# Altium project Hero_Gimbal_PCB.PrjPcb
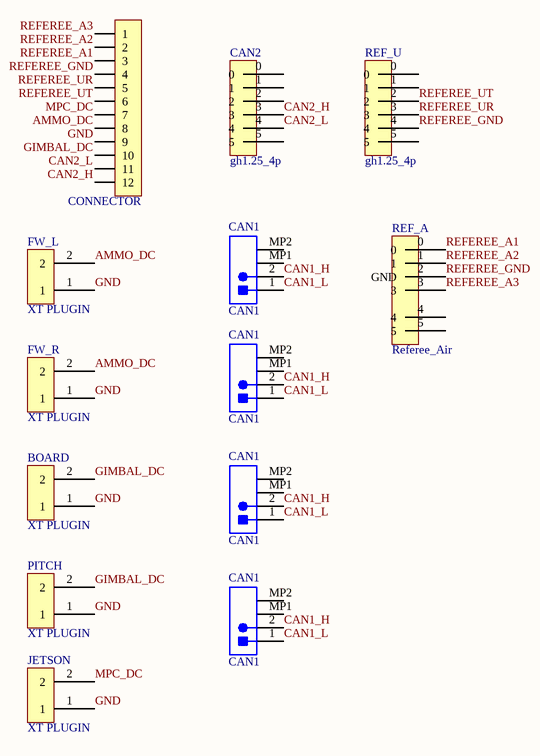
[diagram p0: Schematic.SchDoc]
1 sheet, 13 parts. Net scope: global (net labels, ports and power ports of the same name join across sheets).
Board file: hero gimbal pcb.PcbDoc

## Sheet Schematic.SchDoc
size A4

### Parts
(Parts that share a designator on the sheet are numbered #1, #2 ... from top to bottom, then left to right.)
BOARD  XT PLUGIN  [XT30-M]
CAN1#1  CAN1  [JST-BM02B-GHS-TBT_V]
CAN1#2  CAN1  [JST-BM02B-GHS-TBT_V]
CAN1#3  CAN1  [JST-BM02B-GHS-TBT_V]
CAN1#4  CAN1  [JST-BM02B-GHS-TBT_V]
CAN2  gh1.25_4p  [GH1.25-LS-4P]
CONNECTOR  HDR-1X12  [KF2EDGK5.08-LI-12P]  (value not drawn)
FW_L  XT PLUGIN  [XT30-M]
FW_R  XT PLUGIN  [XT30-M]
JETSON  XT PLUGIN  [XT30-M]
PITCH  XT PLUGIN  [XT30-M]
REF_A  Referee_Air  [M8 Connector]
REF_U  gh1.25_4p  [GH1.25-LS-4P]

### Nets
AMMO_DC: CONNECTOR.8 FW_L.2 FW_R.2
CAN1_H: CAN1#1.2 CAN1#2.2 CAN1#3.2 CAN1#4.2
CAN1_L: CAN1#1.1 CAN1#2.1 CAN1#3.1 CAN1#4.1
CAN2_H: CAN2.3 CONNECTOR.12
CAN2_L: CAN2.4 CONNECTOR.11
GIMBAL_DC: BOARD.2 CONNECTOR.10 PITCH.2
GND: BOARD.1 CONNECTOR.9 FW_L.1 FW_R.1 JETSON.1 PITCH.1
MPC_DC: CONNECTOR.7 JETSON.2
REFEREE_A1: CONNECTOR.3 REF_A.0
REFEREE_A2: CONNECTOR.2 REF_A.1
REFEREE_A3: CONNECTOR.1 REF_A.3
REFEREE_GND: CONNECTOR.4 REF_A.2(GND) REF_U.4
REFEREE_UR: CONNECTOR.5 REF_U.3
REFEREE_UT: CONNECTOR.6 REF_U.2

Not connected (* = marked no-connect by the designer): CAN1#1 MP1 MP2; CAN1#2 MP1 MP2; CAN1#3 MP1 MP2; CAN1#4 MP1 MP2; CAN2 0 1 2 5; REF_A 4 5; REF_U 0 1 5

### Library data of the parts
CAN1#1-CAN1#4 = CMP-2000-05957-1: Disconnectable Crimp Style Connector, Pitch 1.25 mm, 1 x 2 Position, Height 4.05 mm, -25 to 85 degC, RoHS, Tape and Reel; Manufacturer: JST-Sales-America-Inc.; Connector Type: Header,Shrouded; Number of Positions Loaded: All; Pitch: 0.049"(1.25mm); Number of Positions: 2
CONNECTOR = Header 12: 12P接插件; 版权归属: 封装库来自淘宝卖家 ID：黄晶宝石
